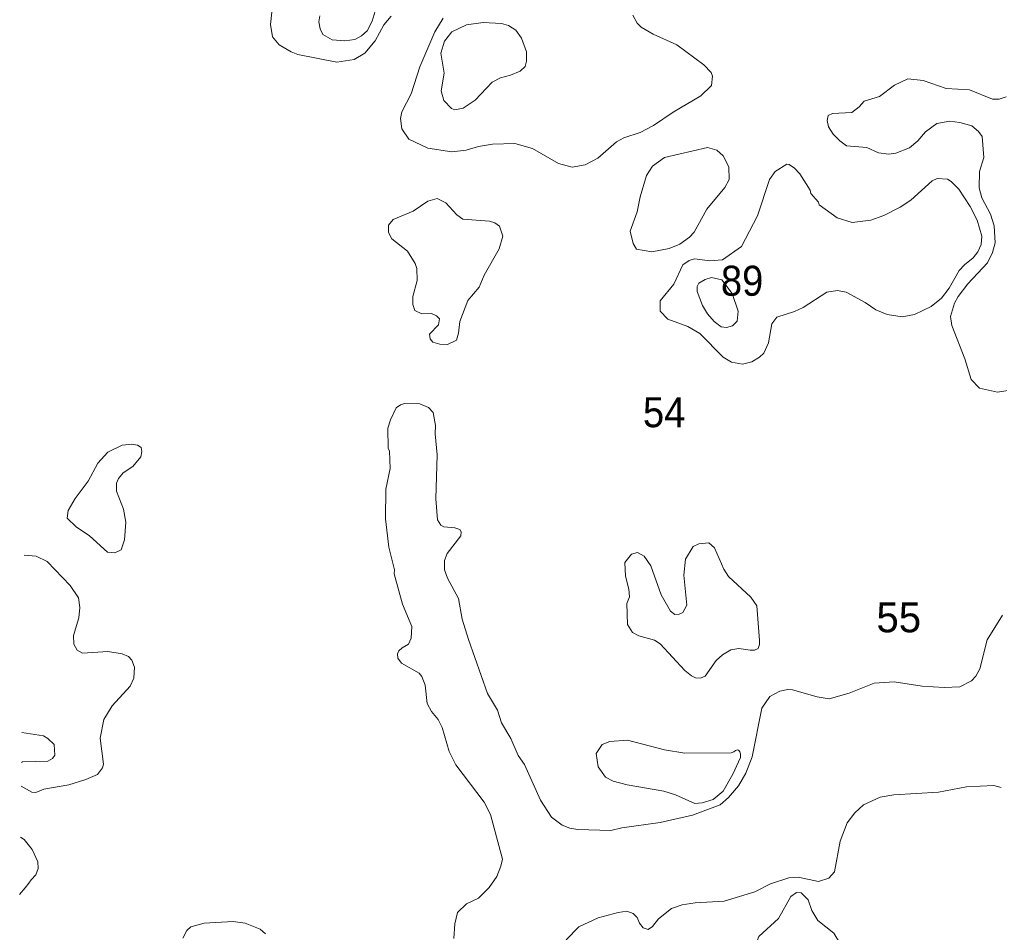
# Model space of a CAD drawing. Extents: x 673.6 to 698.9, y 7012 to 7040.1.
# Drawn here: x 673.81 to 676.422, y 7024.299 to 7026.731 of the extents above; entities that cross this region are included whole.
import ezdxf

# ---------------------------------------------------------------- set-up
doc = ezdxf.new("R2010")
doc.units = 0
doc.header["$LTSCALE"] = 0.032
doc.layers.add('2', color=7, linetype='Continuous', lineweight=13)
doc.layers.add('21', color=7, linetype='Continuous')

msp = doc.modelspace()

# ---------------------------------------------------------------- linework, layer by layer
at = {"layer": '2'}
for points in [[(674.763, 7026.7711), (674.7499, 7026.7271), (674.7362, 7026.7014), (674.7218, 7026.6876), (674.7034, 7026.6779), (674.6771, 7026.6748), (674.6429, 7026.6775), (674.6184, 7026.6916), (674.6108, 7026.7066), (674.6079, 7026.7254), (674.6105, 7026.741)], [(674.4824, 7026.7513), (674.4789, 7026.718), (674.484, 7026.6853), (674.5016, 7026.6637), (674.5336, 7026.645), (674.552, 7026.6386), (674.656, 7026.6174), (674.7014, 7026.625), (674.7301, 7026.642), (674.758, 7026.6745), (674.7809, 7026.717), (674.8004, 7026.74)], [(674.9387, 7026.7346), (674.917, 7026.6983), (674.8769, 7026.6049), (674.8535, 7026.5336), (674.8287, 7026.4851), (674.8256, 7026.4679), (674.8293, 7026.4401), (674.8476, 7026.4124), (674.8981, 7026.3882), (674.9624, 7026.3791), (675.0002, 7026.3832), (675.0331, 7026.3935), (675.0702, 7026.3995), (675.1305, 7026.4011), (675.1776, 7026.3879), (675.2461, 7026.348), (675.2825, 7026.338), (675.3173, 7026.3438), (675.3509, 7026.3616), (675.4008, 7026.4054), (675.4205, 7026.416), (675.4646, 7026.4306), (675.4998, 7026.449), (675.5523, 7026.4844), (675.6263, 7026.528), (675.6539, 7026.5559), (675.6573, 7026.5803), (675.6537, 7026.5903), (675.6342, 7026.6107), (675.5616, 7026.6635), (675.4984, 7026.6925), (675.4664, 7026.7113), (675.4565, 7026.7221), (675.4447, 7026.7434)], [(676.4402, 7026.5255), (676.4212, 7026.5195), (676.4031, 7026.5188), (676.3423, 7026.5442), (676.2798, 7026.5475), (676.2187, 7026.569), (676.178, 7026.5736), (676.1424, 7026.5567), (676.102, 7026.5266), (676.0614, 7026.5137), (676.0478, 7026.4984), (676.0283, 7026.4834), (675.9765, 7026.4809), (675.9654, 7026.4756), (675.963, 7026.4619), (675.9666, 7026.4457), (675.979, 7026.4262), (675.9961, 7026.4084), (676.0146, 7026.3949), (676.0688, 7026.3907), (676.0996, 7026.3765), (676.1273, 7026.3724), (676.1453, 7026.375), (676.1823, 7026.3899), (676.2045, 7026.4078), (676.2245, 7026.4318), (676.2547, 7026.454)], [(676.2547, 7026.454), (676.2893, 7026.4604), (676.316, 7026.4571), (676.3481, 7026.4477), (676.3663, 7026.4331), (676.3756, 7026.42)], [(676.3756, 7026.42), (676.3803, 7026.3642), (676.369, 7026.3268), (676.3682, 7026.283), (676.3752, 7026.2559), (676.3976, 7026.213), (676.4079, 7026.1817), (676.4108, 7026.1365), (676.4033, 7026.1108), (676.39, 7026.083), (676.3379, 7026.0276), (676.3118, 7025.9934), (676.3021, 7025.9758), (676.2917, 7025.9405), (676.2951, 7025.9164), (676.3299, 7025.8274), (676.3462, 7025.7727), (676.369, 7025.7495), (676.4165, 7025.7381), (676.5343, 7025.757)], [(674.877, 7025.7074), (674.8356, 7025.7079), (674.8252, 7025.705), (674.8137, 7025.697), (674.7983, 7025.6645), (674.792, 7025.6427)], [(676.4303, 7025.1444), (676.3893, 7025.0787), (676.3695, 7025.0015), (676.3588, 7024.9818), (676.3476, 7024.9691), (676.316, 7024.9532), (676.2744, 7024.9516), (676.2157, 7024.955), (676.1414, 7024.9665), (676.0878, 7024.9631), (676.021, 7024.9364), (675.9683, 7024.9213), (675.9362, 7024.9267), (675.87, 7024.9458), (675.8577, 7024.9467), (675.8361, 7024.942), (675.8095, 7024.928), (675.7888, 7024.8964), (675.7625, 7024.7671), (675.7458, 7024.7237), (675.726, 7024.6893), (675.6994, 7024.6585), (675.6773, 7024.6394), (675.6035, 7024.6112), (675.5179, 7024.5918), (675.4155, 7024.578), (675.3862, 7024.5704), (675.2982, 7024.5737), (675.2764, 7024.5773), (675.2564, 7024.5851), (675.2277, 7024.6064), (675.1989, 7024.6514), (675.156, 7024.7467), (675.1392, 7024.7707), (675.1192, 7024.8156), (675.0948, 7024.8578), (675.0836, 7024.8916), (675.0574, 7024.9361), (675.0062, 7025.0797), (674.99, 7025.1336), (674.9801, 7025.1891), (674.9506, 7025.2434), (674.9427, 7025.2652), (674.9424, 7025.2899), (674.9495, 7025.3085), (674.9865, 7025.3562), (674.9868, 7025.3661), (674.9831, 7025.3722), (674.9699, 7025.3773), (674.9408, 7025.3798), (674.9324, 7025.3846), (674.9241, 7025.3985), (674.9193, 7025.4546), (674.9234, 7025.5712), (674.9177, 7025.6276), (674.9184, 7025.6493), (674.9126, 7025.684), (674.9, 7025.698), (674.877, 7025.7074)], [(674.792, 7025.6427), (674.7927, 7025.5893), (674.7961, 7025.5816), (674.7978, 7025.5351), (674.7863, 7025.4804), (674.7849, 7025.4013), (674.7944, 7025.3259), (674.8091, 7025.265), (674.8084, 7025.2549), (674.8308, 7025.1736), (674.8551, 7025.1138), (674.8535, 7025.0827), (674.8464, 7025.0671), (674.8296, 7025.0572), (674.8206, 7025.0497), (674.8176, 7025.0414), (674.8184, 7025.0299), (674.8282, 7025.0167), (674.8749, 7024.9902), (674.8823, 7024.9812), (674.8913, 7024.9578), (674.8967, 7024.9092), (674.9083, 7024.8877), (674.926, 7024.8667), (674.936, 7024.8449), (674.9553, 7024.7815), (674.9724, 7024.7452), (675.0483, 7024.6463), (675.0656, 7024.613), (675.0969, 7024.4947), (675.0928, 7024.476), (675.082, 7024.4479), (675.0618, 7024.4185), (675.0333, 7024.39), (675.0009, 7024.3752), (674.9771, 7024.352), (674.9703, 7024.322), (674.9671, 7024.2826)], [(673.814, 7024.6888), (673.8429, 7024.6731), (673.8534, 7024.6716), (673.8744, 7024.6804), (673.9409, 7024.6923), (673.9863, 7024.7063), (674.0177, 7024.7198), (674.031, 7024.7373), (674.0334, 7024.7471), (674.0244, 7024.8171), (674.0345, 7024.866), (674.0567, 7024.9026), (674.1045, 7024.9556), (674.1147, 7024.9768), (674.1162, 7025.0062), (674.1092, 7025.0245), (674.1002, 7025.0345), (674.0838, 7025.0415), (674.0453, 7025.0478), (673.9781, 7025.0428), (673.9632, 7025.0507), (673.9549, 7025.0669), (673.9538, 7025.0901), (673.9679, 7025.1372), (673.9709, 7025.1652), (673.9668, 7025.1905), (673.9444, 7025.2237), (673.8839, 7025.2877), (673.8544, 7025.3019), (673.8224, 7025.3039)], [(673.8148, 7024.7518), (673.8179, 7024.7534), (673.8849, 7024.7551), (673.8975, 7024.7625), (673.9036, 7024.7712), (673.9018, 7024.7995), (673.8857, 7024.8156), (673.8734, 7024.8225), (673.8159, 7024.8315)], [(675.9976, 7024.5421), (676.0157, 7024.5911), (676.0365, 7024.6178), (676.0593, 7024.6395), (676.1043, 7024.6599), (676.1405, 7024.6656), (676.2593, 7024.6729), (676.3341, 7024.687), (676.4071, 7024.691), (676.4264, 7024.6853)], [(673.81, 7024.4002), (673.8247, 7024.4175), (673.8345, 7024.4302), (673.8405, 7024.4392), (673.8532, 7024.4527), (673.8594, 7024.4696), (673.8588, 7024.4875), (673.8438, 7024.5199), (673.8222, 7024.5465), (673.8121, 7024.5532)], [(675.8605, 7024.4445), (675.8857, 7024.4462), (675.9399, 7024.4348), (675.9669, 7024.4436), (675.9826, 7024.4606), (675.9976, 7024.5421)], [(675.267, 7024.2792), (675.3003, 7024.3139), (675.3518, 7024.3379), (675.4052, 7024.3525), (675.429, 7024.3559), (675.4455, 7024.3491), (675.4566, 7024.3385), (675.462, 7024.324), (675.4721, 7024.3112), (675.4855, 7024.3067), (675.4968, 7024.3145), (675.5129, 7024.3356), (675.5476, 7024.363), (675.5758, 7024.3725), (675.6109, 7024.378), (675.6885, 7024.3822), (675.77, 7024.4074), (675.812, 7024.4284), (675.8605, 7024.4445)], [(674.4657, 7024.2952), (674.4516, 7024.3077), (674.4114, 7024.3234), (674.3793, 7024.3279), (674.3024, 7024.3237), (674.2663, 7024.3139), (674.2561, 7024.3041), (674.2448, 7024.2838)]]:
    msp.add_lwpolyline(points, dxfattribs=at)
for points in [[(675.1184, 7026.5828), (675.1439, 7026.594), (675.1572, 7026.6062), (675.1609, 7026.6207), (675.1609, 7026.6453), (675.148, 7026.6819), (675.1326, 7026.7031), (675.1134, 7026.7155), (675.0944, 7026.7209), (675.0458, 7026.7232), (675.0015, 7026.7176), (674.9618, 7026.6982), (674.943, 7026.6737), (674.9325, 7026.6414), (674.9414, 7026.5884), (674.9334, 7026.5412), (674.9406, 7026.5158), (674.9614, 7026.4944), (674.9698, 7026.4909), (674.9924, 7026.495), (675.0242, 7026.5169), (675.0699, 7026.5643), (675.0919, 7026.5762)], [(675.6419, 7026.226), (675.6901, 7026.2842), (675.7016, 7026.3052), (675.7008, 7026.3389), (675.6858, 7026.3682), (675.6686, 7026.3831), (675.6433, 7026.3906), (675.5287, 7026.364), (675.4968, 7026.3403), (675.481, 7026.3155), (675.464, 7026.2589), (675.4565, 7026.2189), (675.4379, 7026.1674), (675.4453, 7026.1342), (675.4541, 7026.1199), (675.4949, 7026.112), (675.5415, 7026.1217), (675.5695, 7026.133), (675.5961, 7026.1513), (675.6077, 7026.1651)], [(676.3439, 7026.2328), (676.3136, 7026.2791), (676.2933, 7026.3001), (676.2832, 7026.3058), (676.2556, 7026.3074), (676.2423, 7026.3017), (676.1854, 7026.2497), (676.1576, 7026.2314), (676.1138, 7026.2096), (676.0787, 7026.1969), (676.0297, 7026.191), (675.9897, 7026.2034), (675.9414, 7026.2379), (675.9397, 7026.2444), (675.9195, 7026.2674), (675.9169, 7026.2764), (675.8896, 7026.3201), (675.8758, 7026.3354), (675.8613, 7026.3451), (675.8548, 7026.3458), (675.8238, 7026.3269), (675.8087, 7026.3055), (675.7768, 7026.2086), (675.7344, 7026.1268), (675.684, 7026.0908), (675.6496, 7026.0882), (675.6094, 7026.0938), (675.5945, 7026.0895), (675.5776, 7026.0781), (675.5541, 7026.0267), (675.5177, 7025.9817), (675.5177, 7025.9539), (675.5379, 7025.9333), (675.5912, 7025.9133), (675.6235, 7025.8949), (675.6855, 7025.8316), (675.7072, 7025.8185), (675.7372, 7025.813), (675.7617, 7025.8192), (675.7819, 7025.8314), (675.7938, 7025.8427), (675.8061, 7025.8702), (675.815, 7025.9202), (675.8287, 7025.9382), (675.8758, 7025.9531), (675.8989, 7025.964), (675.962, 7026.0052), (675.9898, 7026.0093), (676.0132, 7026.0054), (676.0642, 7025.9775), (676.0924, 7025.9576), (676.1225, 7025.9459), (676.1623, 7025.9395), (676.1957, 7025.9457), (676.2395, 7025.9672), (676.2678, 7025.9886), (676.2882, 7026.0152), (676.3143, 7026.0624), (676.3284, 7026.078), (676.3521, 7026.0968), (676.3645, 7026.1122), (676.3729, 7026.1316), (676.3753, 7026.1545), (676.3628, 7026.1972)], [(675.005, 7025.983), (675.0347, 7026.0181), (675.0485, 7026.0507), (675.0881, 7026.1204), (675.0985, 7026.1541), (675.0895, 7026.1806), (675.0767, 7026.1898), (675.0623, 7026.1941), (674.9914, 7026.1993), (674.9754, 7026.2111), (674.9464, 7026.2426), (674.9232, 7026.2542), (674.8984, 7026.2477), (674.8588, 7026.2206), (674.806, 7026.1982), (674.7937, 7026.1833), (674.7929, 7026.1637), (674.8018, 7026.1474), (674.8436, 7026.1144), (674.8644, 7026.0811), (674.8692, 7026.0681), (674.8701, 7026.0362), (674.8586, 7025.9936), (674.8586, 7025.9718), (674.8635, 7025.9561), (674.8824, 7025.947), (674.9083, 7025.9484), (674.9217, 7025.9423), (674.9291, 7025.934), (674.927, 7025.9179), (674.9029, 7025.8929), (674.9042, 7025.8802), (674.9115, 7025.8717), (674.9304, 7025.866), (674.9509, 7025.8653), (674.9743, 7025.8771), (674.9801, 7025.8958), (674.9834, 7025.9267)], [(675.7253, 7025.954), (675.7098, 7026.0015), (675.6818, 7026.0379), (675.6543, 7026.0437), (675.6375, 7026.0388), (675.6209, 7026.0286), (675.6163, 7026.0201), (675.6162, 7026.0064), (675.6305, 7025.9692), (675.6437, 7025.9475), (675.6616, 7025.9268), (675.6805, 7025.913), (675.6941, 7025.9108), (675.7102, 7025.9151), (675.7227, 7025.9279)], [(673.9959, 7025.3557), (674.0447, 7025.3118), (674.0637, 7025.3109), (674.0805, 7025.3185), (674.0893, 7025.3452), (674.0934, 7025.392), (674.087, 7025.4268), (674.068, 7025.4752), (674.068, 7025.4958), (674.0733, 7025.5084), (674.0865, 7025.5238), (674.1121, 7025.5406), (674.1333, 7025.5665), (674.136, 7025.5804), (674.1344, 7025.5911), (674.1244, 7025.5973), (674.1089, 7025.6001), (674.0831, 7025.5975), (674.0455, 7025.5784), (674.0182, 7025.5492), (673.9924, 7025.5018), (673.9582, 7025.4555), (673.9394, 7025.423), (673.9365, 7025.4031), (673.9606, 7025.3795)], [(675.4353, 7025.1928), (675.4338, 7025.2135), (675.4247, 7025.248), (675.4236, 7025.2849), (675.4412, 7025.3065), (675.4572, 7025.3114), (675.4747, 7025.3019), (675.4929, 7025.2762), (675.5202, 7025.1987), (675.5451, 7025.1553), (675.5565, 7025.1465), (675.5681, 7025.1472), (675.5778, 7025.1518), (675.5882, 7025.1714), (675.5808, 7025.2511), (675.5852, 7025.2934), (675.6055, 7025.327), (675.6206, 7025.3345), (675.6473, 7025.3369), (675.6627, 7025.324), (675.6875, 7025.2668), (675.7, 7025.2476), (675.7594, 7025.1921), (675.7755, 7025.1689), (675.7822, 7025.0772), (675.782, 7025.0662), (675.7783, 7025.0557), (675.7693, 7025.0512), (675.757, 7025.0511), (675.7272, 7025.056), (675.7062, 7025.0517), (675.6838, 7025.0389), (675.6669, 7025.0236), (675.6375, 7024.9821), (675.625, 7024.9761), (675.6115, 7024.9774), (675.6011, 7024.9824), (675.5835, 7024.9974), (675.5178, 7025.0681), (675.502, 7025.0776), (675.4608, 7025.0894), (675.4433, 7025.0983), (675.4305, 7025.1196), (675.4289, 7025.1756)], [(675.4307, 7024.8112), (675.5293, 7024.7852), (675.583, 7024.7767), (675.707, 7024.7775), (675.7138, 7024.7799), (675.7181, 7024.7834), (675.7238, 7024.7852), (675.7266, 7024.7849), (675.7285, 7024.7831), (675.7299, 7024.7807), (675.7316, 7024.7748), (675.7312, 7024.7655), (675.7113, 7024.7204), (675.685, 7024.6758), (675.6586, 7024.6532), (675.6298, 7024.6442), (675.6096, 7024.6427), (675.5586, 7024.6656), (675.5271, 7024.6756), (675.4298, 7024.6922), (675.392, 7024.7021), (675.3715, 7024.7124), (675.3518, 7024.7401), (675.3466, 7024.7754), (675.3625, 7024.7997), (675.3836, 7024.8078)], [(675.9483, 7024.1365), (675.9862, 7024.1506), (676.0087, 7024.1734), (676.0139, 7024.2063), (675.9981, 7024.2674), (675.9805, 7024.297), (675.9376, 7024.3306), (675.922, 7024.3573), (675.9118, 7024.3857), (675.8937, 7024.4047), (675.881, 7024.4051), (675.8661, 7024.3951), (675.8327, 7024.3359), (675.7803, 7024.2882), (675.7664, 7024.2512), (675.7658, 7024.2274), (675.769, 7024.21), (675.7789, 7024.1898), (675.8153, 7024.1526), (675.8344, 7024.1424), (675.8665, 7024.1357)]]:
    msp.add_lwpolyline(points, close=True, dxfattribs=at)

# ---------------------------------------------------------------- texts
at = {"layer": '21', "width": 0.95}
for s, p in [('89', (675.6794, 7025.9954)), ('54', (675.4716, 7025.6452))]:
    msp.add_text(s, height=0.08, dxfattribs=at).set_placement(p)
at = {"layer": '21'}
msp.add_text('55', height=0.08, dxfattribs=at).set_placement((676.094, 7025.0988))

doc.saveas('drawing.dxf')
